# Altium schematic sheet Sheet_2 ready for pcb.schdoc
size 194 x 119 mm
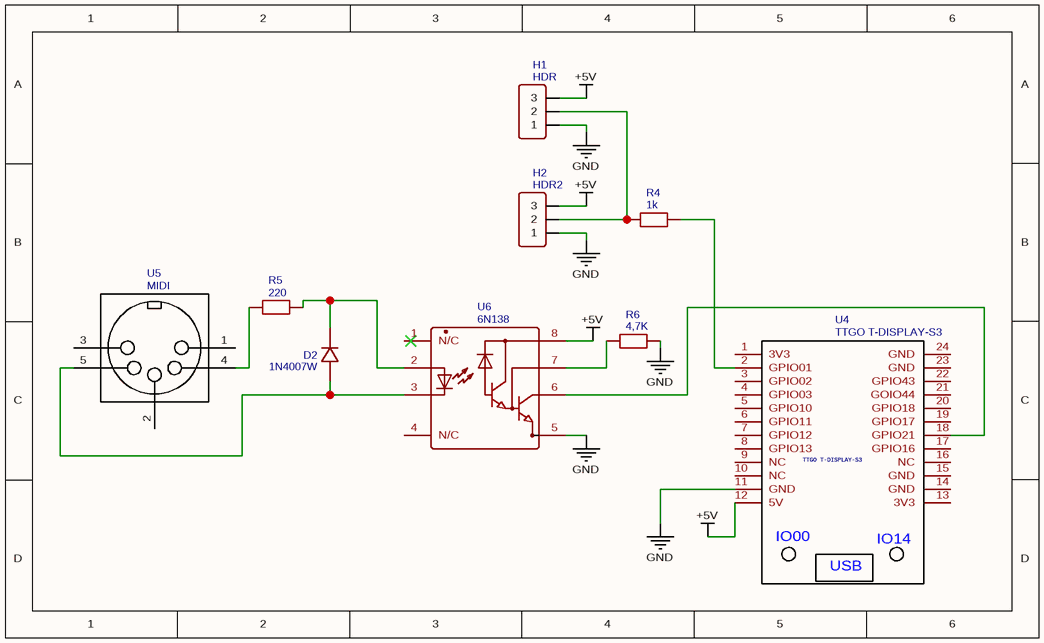
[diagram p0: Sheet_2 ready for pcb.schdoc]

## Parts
D2  1N4007W  [SOD-123_L2.8-W1.8-LS3.7-RD]
H1  HDR  [HDR-F-2.54_1X3]
H2  HDR2  [HDR-F-2.54_1X3]
R4  1k  [R1206-1]
R5  220  [R1206-1]
R6  4,7K  [R1206-1]
U4  TTGO T-DISPLAY-S3  [LILYGO T-DISPLAY-S3-V3]
U5  MIDI  [MIDI]
U6  6N138  [DIP-8_L9.8-W6.6-P2.54-LS7.6-BL]

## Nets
+5V: H1.3 H2.3 U4.12(5V) U6.8(VCC)
GND: H1.1 H2.1 R6.2 U4.11(GND) U6.5(GND)
NetD2_1: D2.1 R5.2 U6.2(A)
NetD2_2: D2.2 U5.5 U6.3(C)
NetH1_2: H1.2 H2.2 R4.1
NetR4_2: R4.2 U4.2(GPIO01)
NetR5_1: R5.1 U5.4
NetR6_1: R6.1 U6.7(VB)
NetU4_18: U4.18(GPIO21) U6.6(VOUT)

Not connected (* = marked no-connect by the designer): U4 1(3V3) 3(GPIO02) 4(GPIO03) 5(GPIO10) 6(GPIO11) 7(GPIO12) 8(GPIO13) 9(NC) 10(NC) 13(3V3) 14(GND) 15(GND) 16(NC) 17(GPIO16) 19(GPIO17) 20(GPIO18) 21(GOIO44) 22(GPIO43) 23(GND) 24(GND); U5 1 2 3; U6 1(N/C) 4(N/C)

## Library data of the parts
D2 = 1N4007W: Manufacturer: BLUE ROCKET; Contributor: LCEDA_Lib
H1 = HDR: Contributor: LCEDA_Lib
H2 = HDR2: Contributor: LCEDA_Lib
R4 = 1k: nameAlias: Value(Ω); Contributor: LCEDA_Lib
R5 = 220: nameAlias: Value(Ω); Contributor: LCEDA_Lib
R6 = 4,7K: nameAlias: Value(Ω); Contributor: LCEDA_Lib
U4 = TTGO T-DISPLAY-S3: Manufacturer: lilygo; Contributor: hrituraj
U5 = MIDI: Contributor: snleal
U6 = 6N138: Manufacturer: ISOCOM(英国安数光); Contributor: LCSC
